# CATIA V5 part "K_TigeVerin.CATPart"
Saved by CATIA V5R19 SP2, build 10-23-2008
Part number: Tige Verin
Bounding box of the stored display mesh (mm): x 0 to 2, y -1 to 12, z -1 to 1
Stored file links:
  G:\Khaled_CFAO_2011\ST2M\ST2M_GR1\bgaltie\bgaltie\Khaled\CAD_thinkMOTION\K_TigeVerin.CATPart
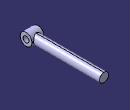
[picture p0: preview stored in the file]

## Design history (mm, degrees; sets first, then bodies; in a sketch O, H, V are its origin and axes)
AxisSystem1: origin (0, 0, 0), X (1, 0, 0), Y (0, 1, 0), Z (0, 0, 1)
Body1 (main body)
  Sketch1 on YZ plane of AxisSystem1, origin (0, 0, 0), H (0, 1, 0), V (0, 0, 1)
    circle A1 centre (0, 0) radius 1
    point P1 (0, 0)
    radius A1 = 1
    coincidence: P1 O
  Pad1: profile Sketch1, direction (1, 0, 0), length 2
  Sketch2 on ZX plane of AxisSystem1, origin (0, 0, 0), H (0, 0, 1), V (1, 0, 0)
    circle A1 centre (0, 1) radius 0.75
    point P1 (0, 1)
    distance O P1 = 1
    radius A1 = 0.75
    coincidence: P1 V
  Pad2: profile Sketch2, direction (0, 1, 0), length 12
  Sketch3 on end face of Pad1, origin (2, 0, 0), H (0, 1, 0), V (0, 0, 1)
    point P1 (0, 0)
    reference projected point E1 (0, 0) from vertex [YZ plane of AxisSystem1 | ZX plane of AxisSystem1 | XY plane of AxisSystem1]
    coincidence: E1 P1
  Hole1: placed by Sketch3, at (2, 0, 0) direction (-1, 0, 0), diameter 1, through (limit type 6)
